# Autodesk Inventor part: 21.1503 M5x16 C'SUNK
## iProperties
Created: 2006-12
Part Number: 21.1503 M5x16 C'SUNK
Material: Steel, Mild
Description: Hexagon socket countersunk head cap screws
Document SubType Name: Modeling
Standard: DIN 7991
Designer: Andy Moles
Standards Organization: DIN
Language: en-US
Size Designation: M5x16
Categories: <MemberInstance Version="R10.0.0"><Categories><Category DisplayName="Fasteners" InternalName="e4da775c-781d-43d5-af7c-5136215cf5a6" Mnemonic="FSTN"><Category Di
Density: 7.86 g/cm^3
Mass: 2.97248 g
Surface Area: 4.18131 cm^2
Volume: 0.378178 cm^3
Author: Andy Moles
Revision Number: 1
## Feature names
1. Revolution1
2. Extrusion1
3. Fillet1
4. Chamfer1
